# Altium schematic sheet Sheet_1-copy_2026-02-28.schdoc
size 377 x 177 mm; Device: Altium_Custom(1484.1806*699.0556); Name: Altium_Custom(1484.1806*699.0556); Width: 1484.1806; Height: 699.0556; X Region Count: 6; Y Region Count: 4; Blade Width: 20; Title Block: 1; Region Start: 1; Border: 1; Title Block Position: 3
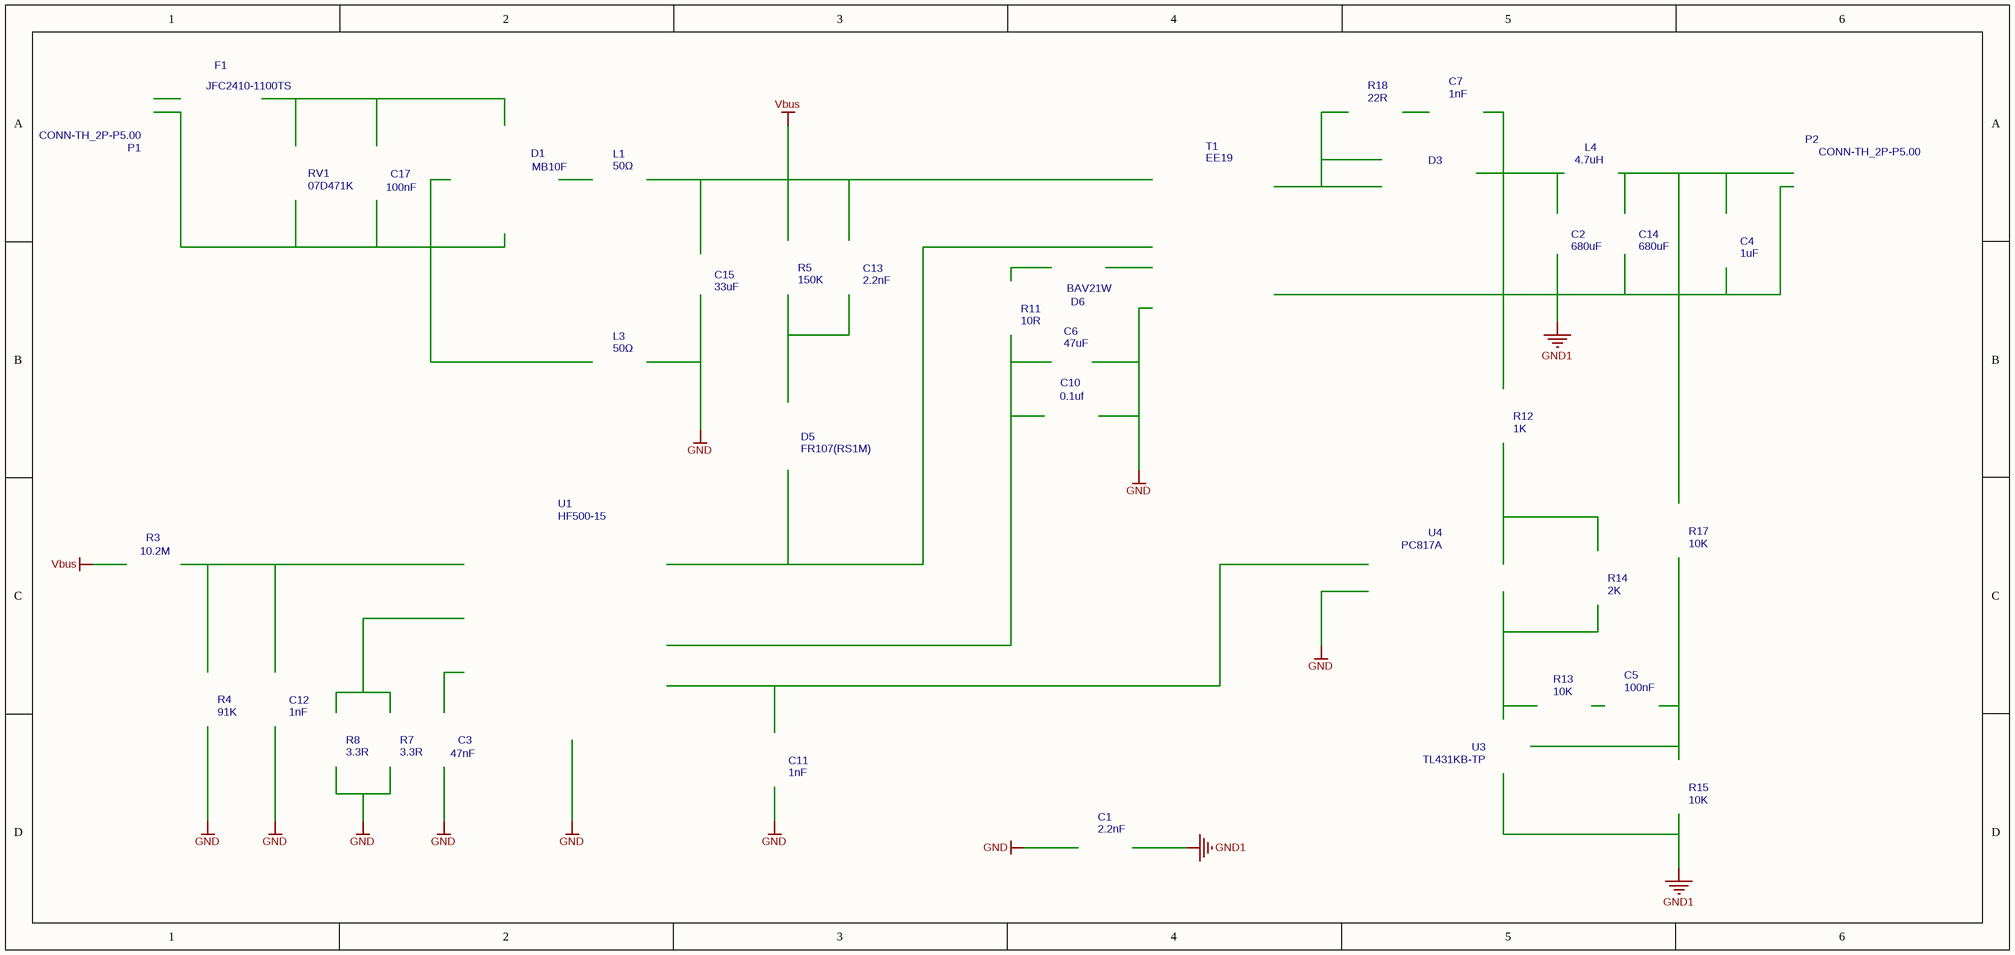
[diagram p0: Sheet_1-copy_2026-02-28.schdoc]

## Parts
C1  2.2nF  [CAP-TH_L10.0-W4.5-P10.00-D0.6-S4.0]
C2  680uF  [CAP-TH_BD8.0-P3.50-D0.6-FD]
C3  47nF  [C0603]
C4  1uF  [C0603]
C5  100nF  [C0603]
C6  47uF  [CAP-TH_BD5.0-P2.00-D0.8-FD]
C7  1nF  [C0805]
C10  0.1uf  [C0603]
C11  1nF  [C0805]
C12  1nF  [C0805]
C13  2.2nF  [C1206]
C14  680uF  [CAP-TH_BD8.0-P3.50-D0.6-FD]
C15  33uF  [CAP-TH_BD10.0-P5.00-D1.0-FD]
C17  100nF  [CAP-TH_L13.0-W6.0-P10.00-D0.6]
D1  MB10F
D3  SB10100L  [TO-277A_L4.7-W6.1-LS6.6-TR]  (value not drawn)
D5  FR107(RS1M)  [SMA_L4.3-W2.6-LS5.2-RD]
D6  BAV21W  [SOD-123_L2.8-W1.8-LS3.7-RD]
F1  JFC2410-1100TS  [F2410]
L1  50Ω  [L1206]
L3  50Ω  [L1206]
L4  4.7uH  [IND-SMD_L7.3-W6.8]
P1  CONN-TH_2P-P5.00  [CONN-TH_2P-P5.00]
P2  CONN-TH_2P-P5.00  [CONN-TH_2P-P5.00]
R3  10.2M  [R1206]
R4  91K  [R0603]
R5  150K  [R1206]
R7  3.3R  [R1206]
R8  3.3R  [R1206]
R11  10R  [R1206]
R12  1K  [R0603]
R13  10K  [R0603]
R14  2K  [R0603]
R15  10K  [R0603]
R17  10K  [R0603]
R18  22R  [R1206]
RV1  07D471K  [RES-TH_L9.0-W6.2-P5.00-D0.7-S6.20]
T1  EE19
U1  HF500-15  [SOP-7_L4.9-W3.9-P1.27-LS6.0-BR]
U3  TL431KB-TP  [SOT-23-3_L2.9-W1.4-P1.91-LS2.6-BR]
U4  PC817A  [SMD-4_L4.6-W6.5-P2.54-LS10.2-BL]

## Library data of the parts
C1 = 2.2nF: Manufacturer: KNSCHA(科尼盛); nameAlias: Value; Contributor: LCSC; UniqueId: 5fb4f22ffcb6a001; AddInBom: yes
C2 = 680uF: Manufacturer: MAN YUE(万裕科技); nameAlias: Value; Contributor: LCSC; UniqueId: 21d50210554cb61f; AddInBom: yes
C3 = 47nF: nameAlias: Value(F); Contributor: LCEDA_Lib; UniqueId: ec64484c8c07847f; AddInBom: yes; ModelId: fca5be93b99f4b5a9a2fd372d58c31d9
C4 = 1uF: nameAlias: Value(F); Contributor: LCEDA_Lib; UniqueId: 623e2bb2442f04df; AddInBom: yes; ModelId: fca5be93b99f4b5a9a2fd372d58c31d9
C5 = 100nF: nameAlias: Value(F); Contributor: LCEDA_Lib; UniqueId: 05d417a4d81547fc; AddInBom: yes; ModelId: fca5be93b99f4b5a9a2fd372d58c31d9
C6 = 47uF: Manufacturer: CX(承兴); nameAlias: Value; UniqueId: d45ffe04e43665a4; AddInBom: yes
C7 = 1nF: nameAlias: Value(F); Contributor: LCEDA_Lib; UniqueId: 3007ca2539a35480; AddInBom: yes
C10 = 0.1uf: nameAlias: Value(F); Contributor: LCEDA_Lib; UniqueId: c1764753ee6525b4; AddInBom: yes; ModelId: fca5be93b99f4b5a9a2fd372d58c31d9
C11 = 1nF: nameAlias: Value(F); Contributor: LCEDA_Lib; UniqueId: b49c3108c5288e9f; AddInBom: yes
C12 = 1nF: nameAlias: Value(F); Contributor: LCEDA_Lib; UniqueId: 4eba2014d94c20ef; AddInBom: yes
C13 = 2.2nF: nameAlias: Value(F); Contributor: LCEDA_Lib; UniqueId: 8d11a04c32f33369; AddInBom: yes
C14 = 680uF: Manufacturer: MAN YUE(万裕科技); nameAlias: Value; Contributor: LCSC; UniqueId: c9f451b8b2c5f180; AddInBom: yes
C15 = 33uF: Manufacturer: CX(承兴); nameAlias: Value; UniqueId: 4a0fa0f8d5a09ecc; AddInBom: yes
C17 = 100nF: Manufacturer: KNSCHA(科尼盛); nameAlias: Value; Contributor: LCSC; UniqueId: 5e7964c847a08933; AddInBom: yes; ModelId: fca5be93b99f4b5a9a2fd372d58c31d9; ModelName: C0603
D1 = MB10F: Contributor: lvhua-lin; UniqueId: 07a0d5848cd81316; AddInBom: yes
D3 = SB10100L: Manufacturer: MDD; Contributor: LCSC; UniqueId: ce0e29427420bb9a; AddInBom: yes
D5 = FR107(RS1M): Manufacturer: KEXIN(科信); Contributor: LCSC; UniqueId: f6a2299b727f22e5; AddInBom: yes; ModelId: 7ed2c9d0a4a74bbdbba07ab4052caf5b
D6 = BAV21W: Manufacturer: CJ(江苏长电/长晶); UniqueId: da39aa9ccad1dedd; AddInBom: yes; ModelId: 7884390a25fb4c08947731ebfba7e3f8
F1 = JFC2410-1100TS: Manufacturer: JDTfuse(集电通); Add into BOM: yes; Type: 贴片式保险丝; Current Rating: 1A; Voltage Rating  (AC): 250V; Breaking Capacity: 50A; Contributor: VH2505660284; UniqueId: 0327748d3d32b991
L1 = 50Ω: Manufacturer: TAI-TECH(台庆); nameAlias: Value; Contributor: LCSC; UniqueId: 2f42939b1ffc8518; AddInBom: yes
L3 = 50Ω: Manufacturer: TAI-TECH(台庆); nameAlias: Value; Contributor: LCSC; UniqueId: 79bb0d6a2d89630c; AddInBom: yes
L4 = 4.7uH: Manufacturer: cjiang(长江微电); nameAlias: Value; Contributor: LCSC; UniqueId: 61c0dfec43001ecc; AddInBom: yes
P1 = CONN-TH_2P-P5.00: Contributor: LCEDA_Lib; UniqueId: f88e3064cb77b82c; AddInBom: yes; ModelId: 82ed0e208d9a4cc2ac854dcad4b56f25
P2 = CONN-TH_2P-P5.00: Contributor: LCEDA_Lib; UniqueId: ddb6c992c6045fb8; AddInBom: yes; ModelId: 82ed0e208d9a4cc2ac854dcad4b56f25
R3 = 10.2M: nameAlias: Value(Ω); Contributor: LCEDA_Lib; UniqueId: 6e26aea592918673; AddInBom: yes
R4 = 91K: nameAlias: Value(Ω); Contributor: LCEDA_Lib; UniqueId: 49359f7360e76581; AddInBom: yes; ModelId: fc143cca1e79419f9cd78b61e9279f08
R5 = 150K: nameAlias: Value(Ω); Contributor: LCEDA_Lib; UniqueId: 96bd3269827a783e; AddInBom: yes
R7 = 3.3R: nameAlias: Value(Ω); Contributor: LCEDA_Lib; UniqueId: 01f5c70ff2630ee7; AddInBom: yes
R8 = 3.3R: nameAlias: Value(Ω); Contributor: LCEDA_Lib; UniqueId: f0665cc51e401020; AddInBom: yes
R11 = 10R: nameAlias: Value(Ω); Contributor: LCEDA_Lib; UniqueId: 069ba0dc55a84bc8; AddInBom: yes
R12 = 1K: nameAlias: Value(Ω); Contributor: LCEDA_Lib; UniqueId: f574a6082c36e6cb; AddInBom: yes; ModelId: fc143cca1e79419f9cd78b61e9279f08
R13 = 10K: nameAlias: Value(Ω); Contributor: LCEDA_Lib; UniqueId: ff7631ddbc1e2fda; AddInBom: yes; ModelId: fc143cca1e79419f9cd78b61e9279f08
R14 = 2K: nameAlias: Value(Ω); Contributor: LCEDA_Lib; UniqueId: d58291ee940aacae; AddInBom: yes; ModelId: fc143cca1e79419f9cd78b61e9279f08
R15 = 10K: nameAlias: Value(Ω); Contributor: LCEDA_Lib; UniqueId: 615753eb74f5e235; AddInBom: yes; ModelId: fc143cca1e79419f9cd78b61e9279f08
R17 = 10K: nameAlias: Value(Ω); Contributor: LCEDA_Lib; UniqueId: 7917acf7ef76b3a3; AddInBom: yes; ModelId: fc143cca1e79419f9cd78b61e9279f08
R18 = 22R: nameAlias: Value(Ω); Contributor: LCEDA_Lib; UniqueId: 1bd7cdeea74e381f; AddInBom: yes
RV1 = 07D471K: Manufacturer: RUILON(瑞隆源); UniqueId: a654f2b78988c931; AddInBom: yes; ModelId: a7c4cca09f9c48ff803b22e34f335ea2
T1 = EE19: Manufacturer: rs; Manufacturer Part: EE19 5+5; Contributor: sunhaoqin; Origin Footprint: EE19 5+5 FT; UniqueId: cf2c480e5945250c; AddInBom: yes
U1 = HF500-15: Manufacturer: MPS; Contributor: sunhaoqin; Package Display: No; UniqueId: 48a4a086d8c42a18; AddInBom: yes; ModelId: 4c4ce7185fd740e384edc3256ac39212
U3 = TL431KB-TP: Manufacturer: MCC(美微科); Contributor: lcsc; UniqueId: eac3f191c372887e; AddInBom: yes; ModelId: 81c748039019403cb7932d7f29d10763
U4 = PC817A: Manufacturer: Wuxi China Resources Huajing Microelectronics; Contributor: LCSC; UniqueId: e5d1bee62801ccc5; AddInBom: yes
